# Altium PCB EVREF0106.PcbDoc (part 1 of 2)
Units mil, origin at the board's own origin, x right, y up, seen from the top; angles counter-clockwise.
Board outline 3543.31 x 1948.82 mil, 4 copper layers (Top Layer, GND, S2, Bottom Layer); 163 components, 42 nets, 581 pads, 707 vias.
Unrouted connection lines stored in the file: 3.
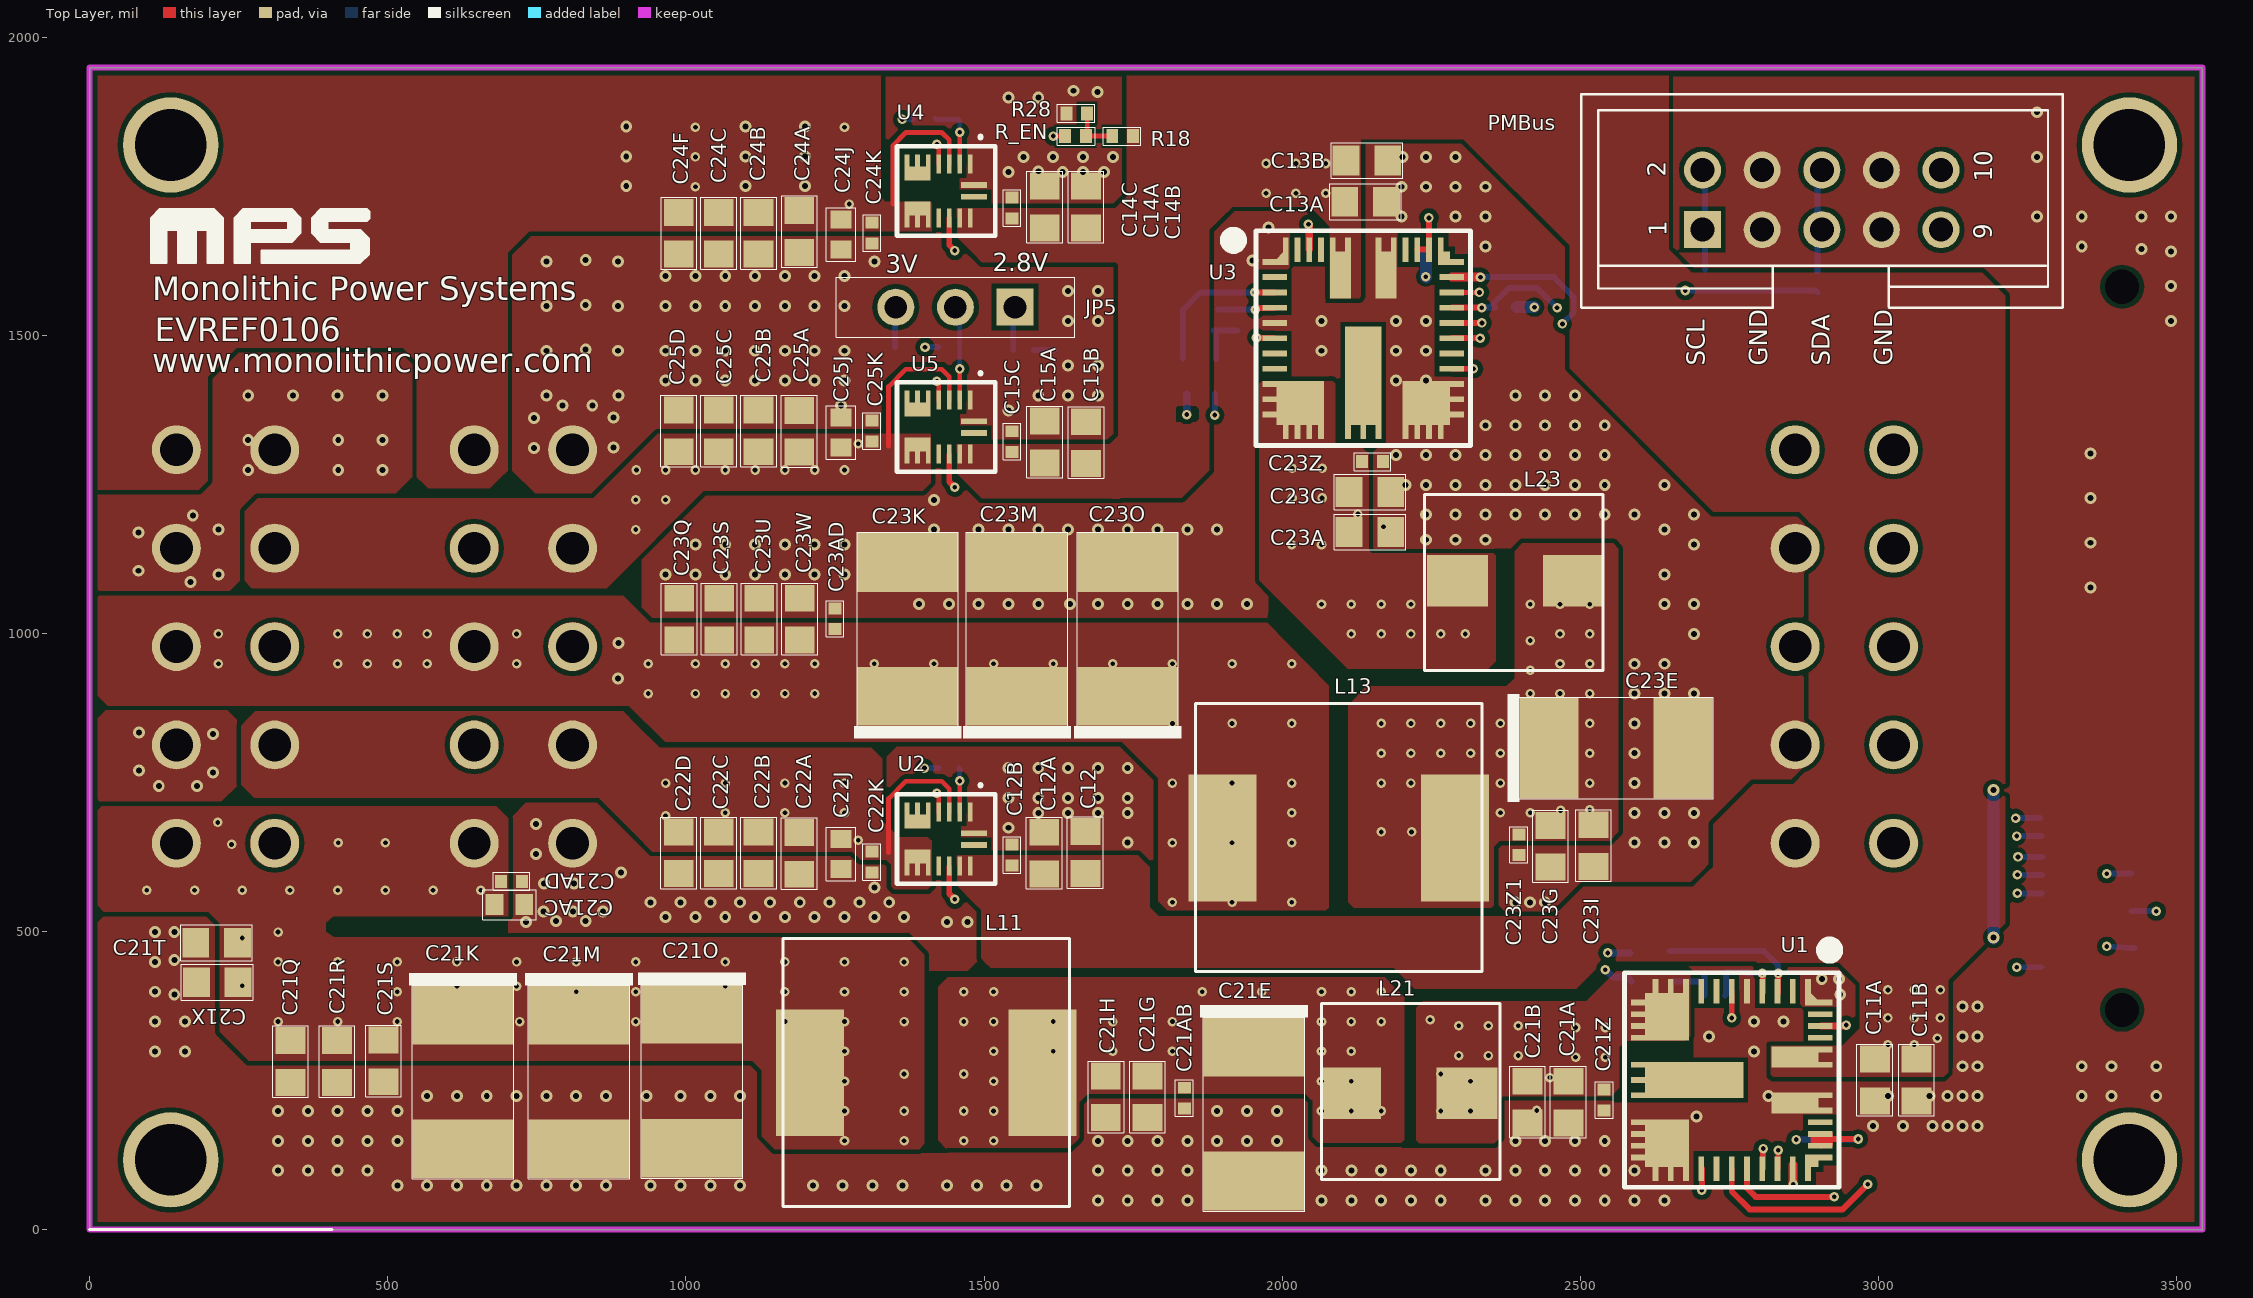
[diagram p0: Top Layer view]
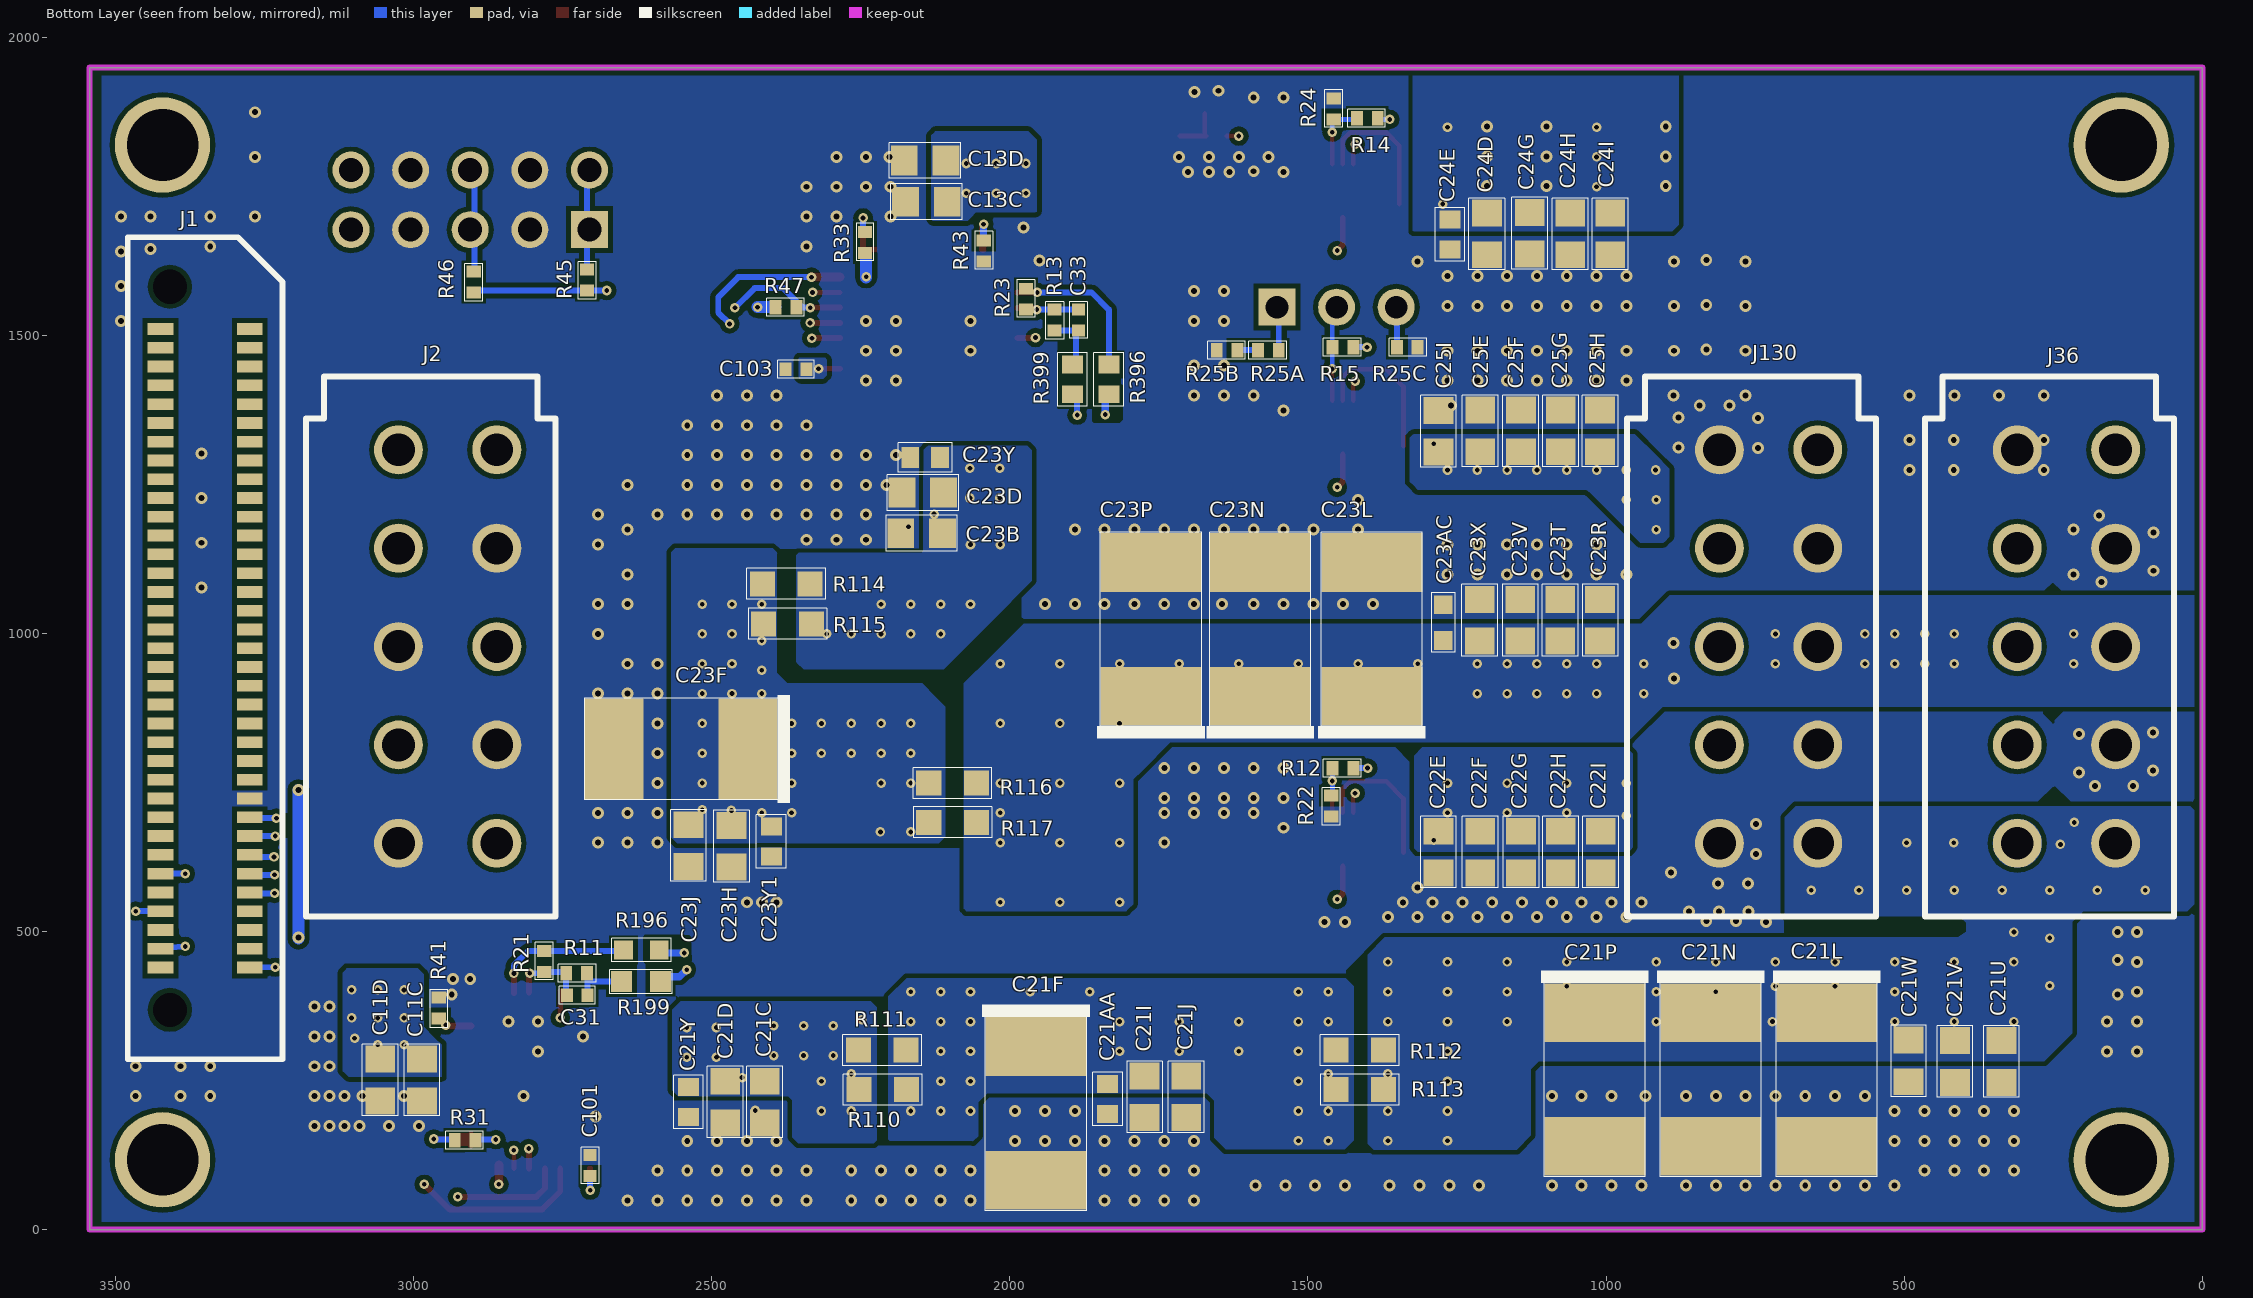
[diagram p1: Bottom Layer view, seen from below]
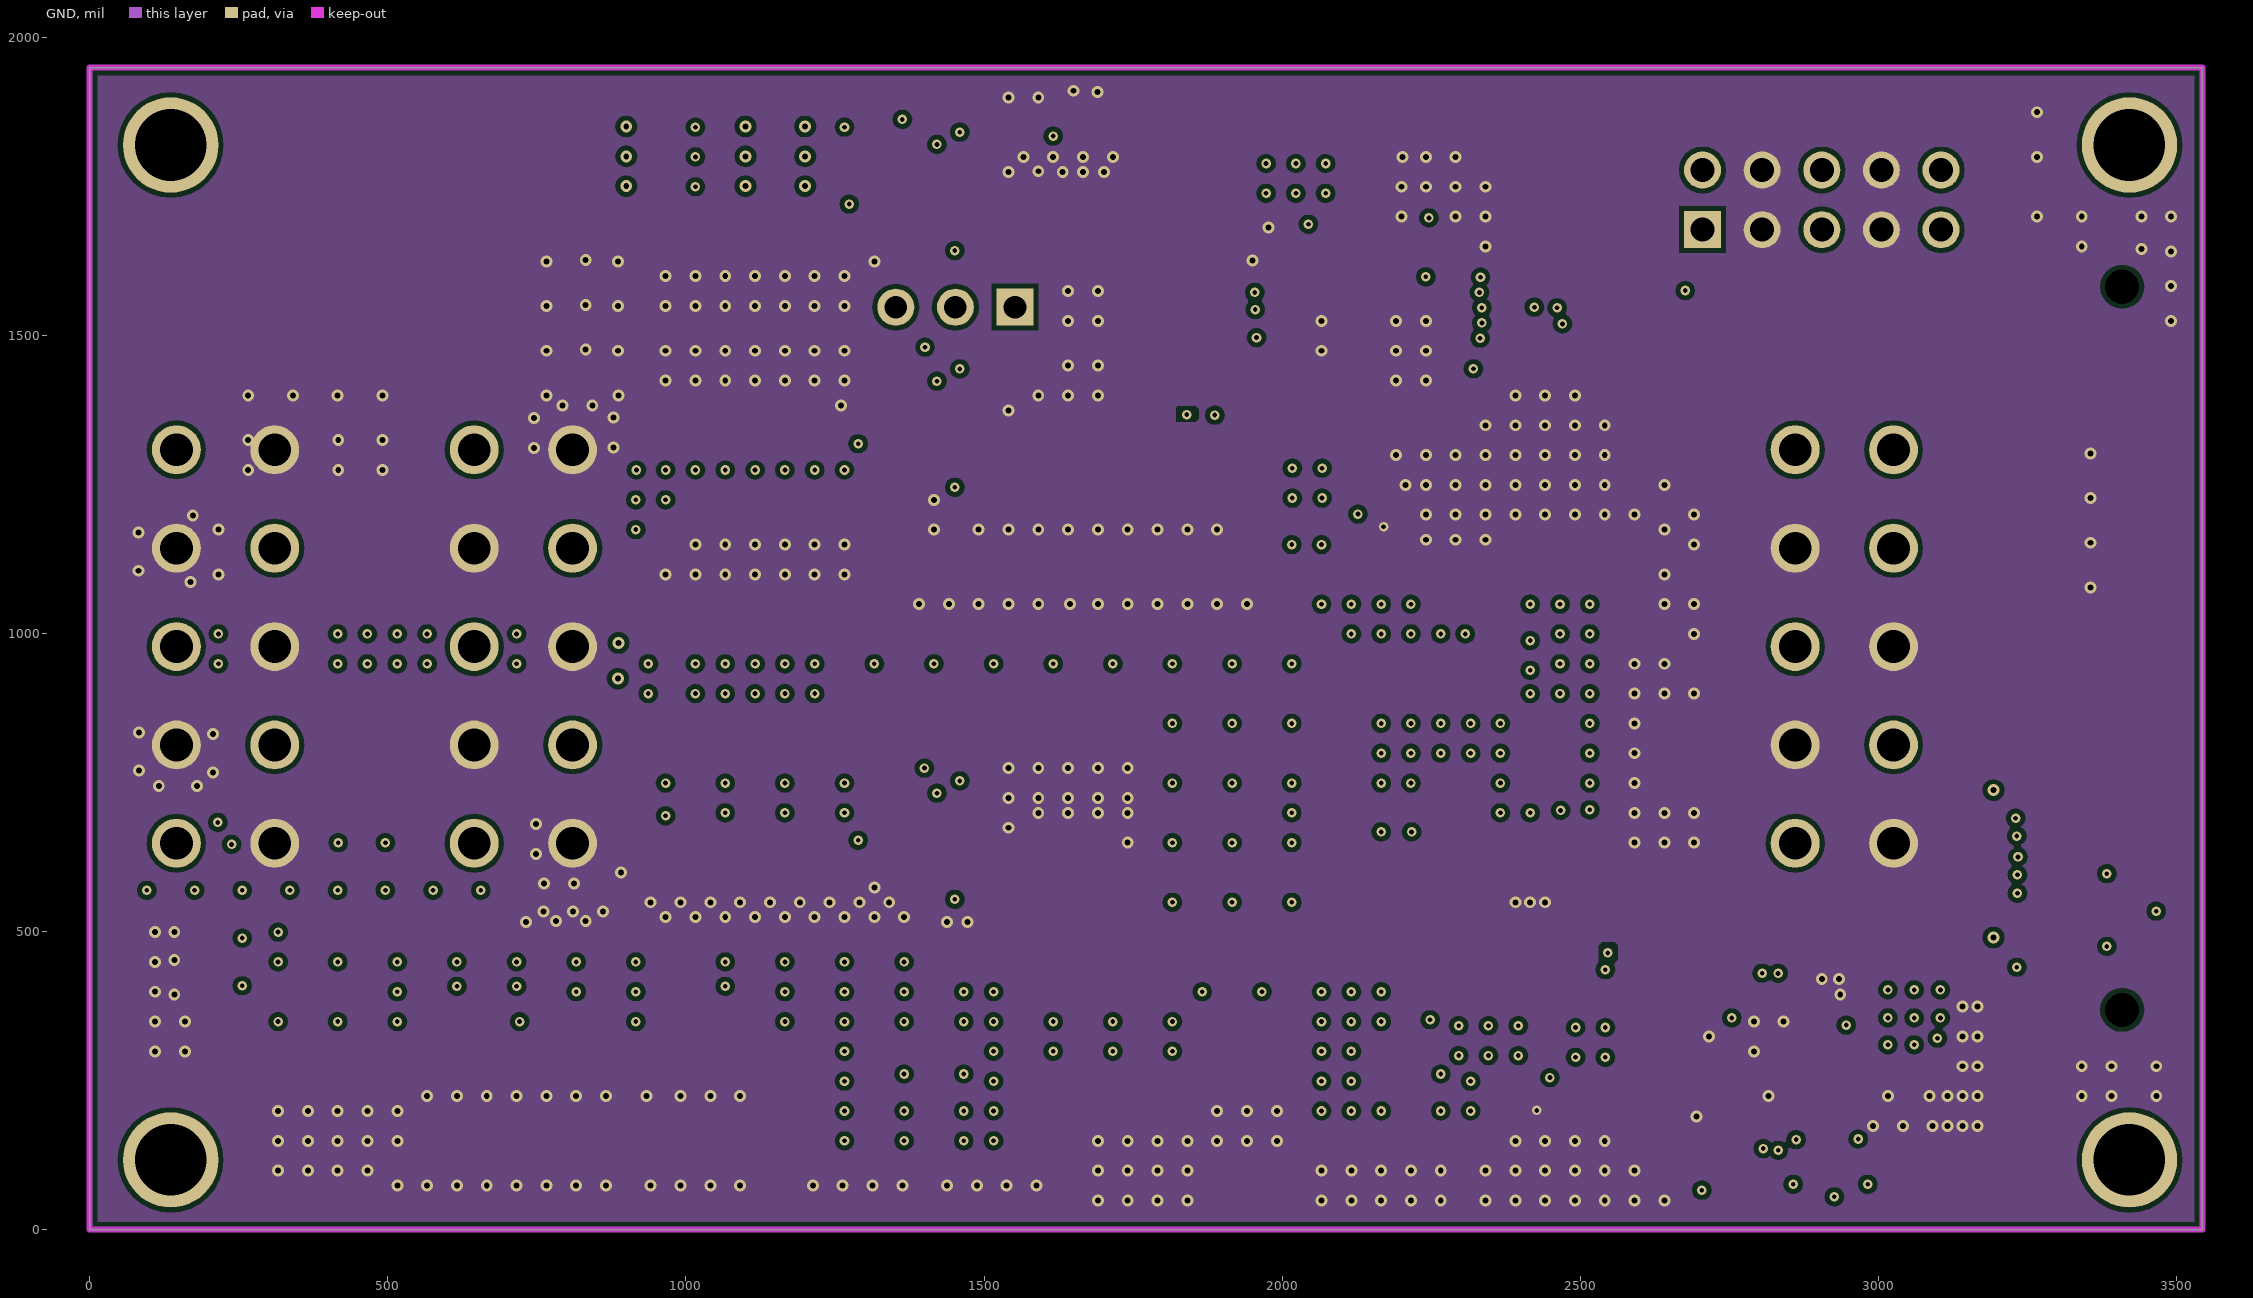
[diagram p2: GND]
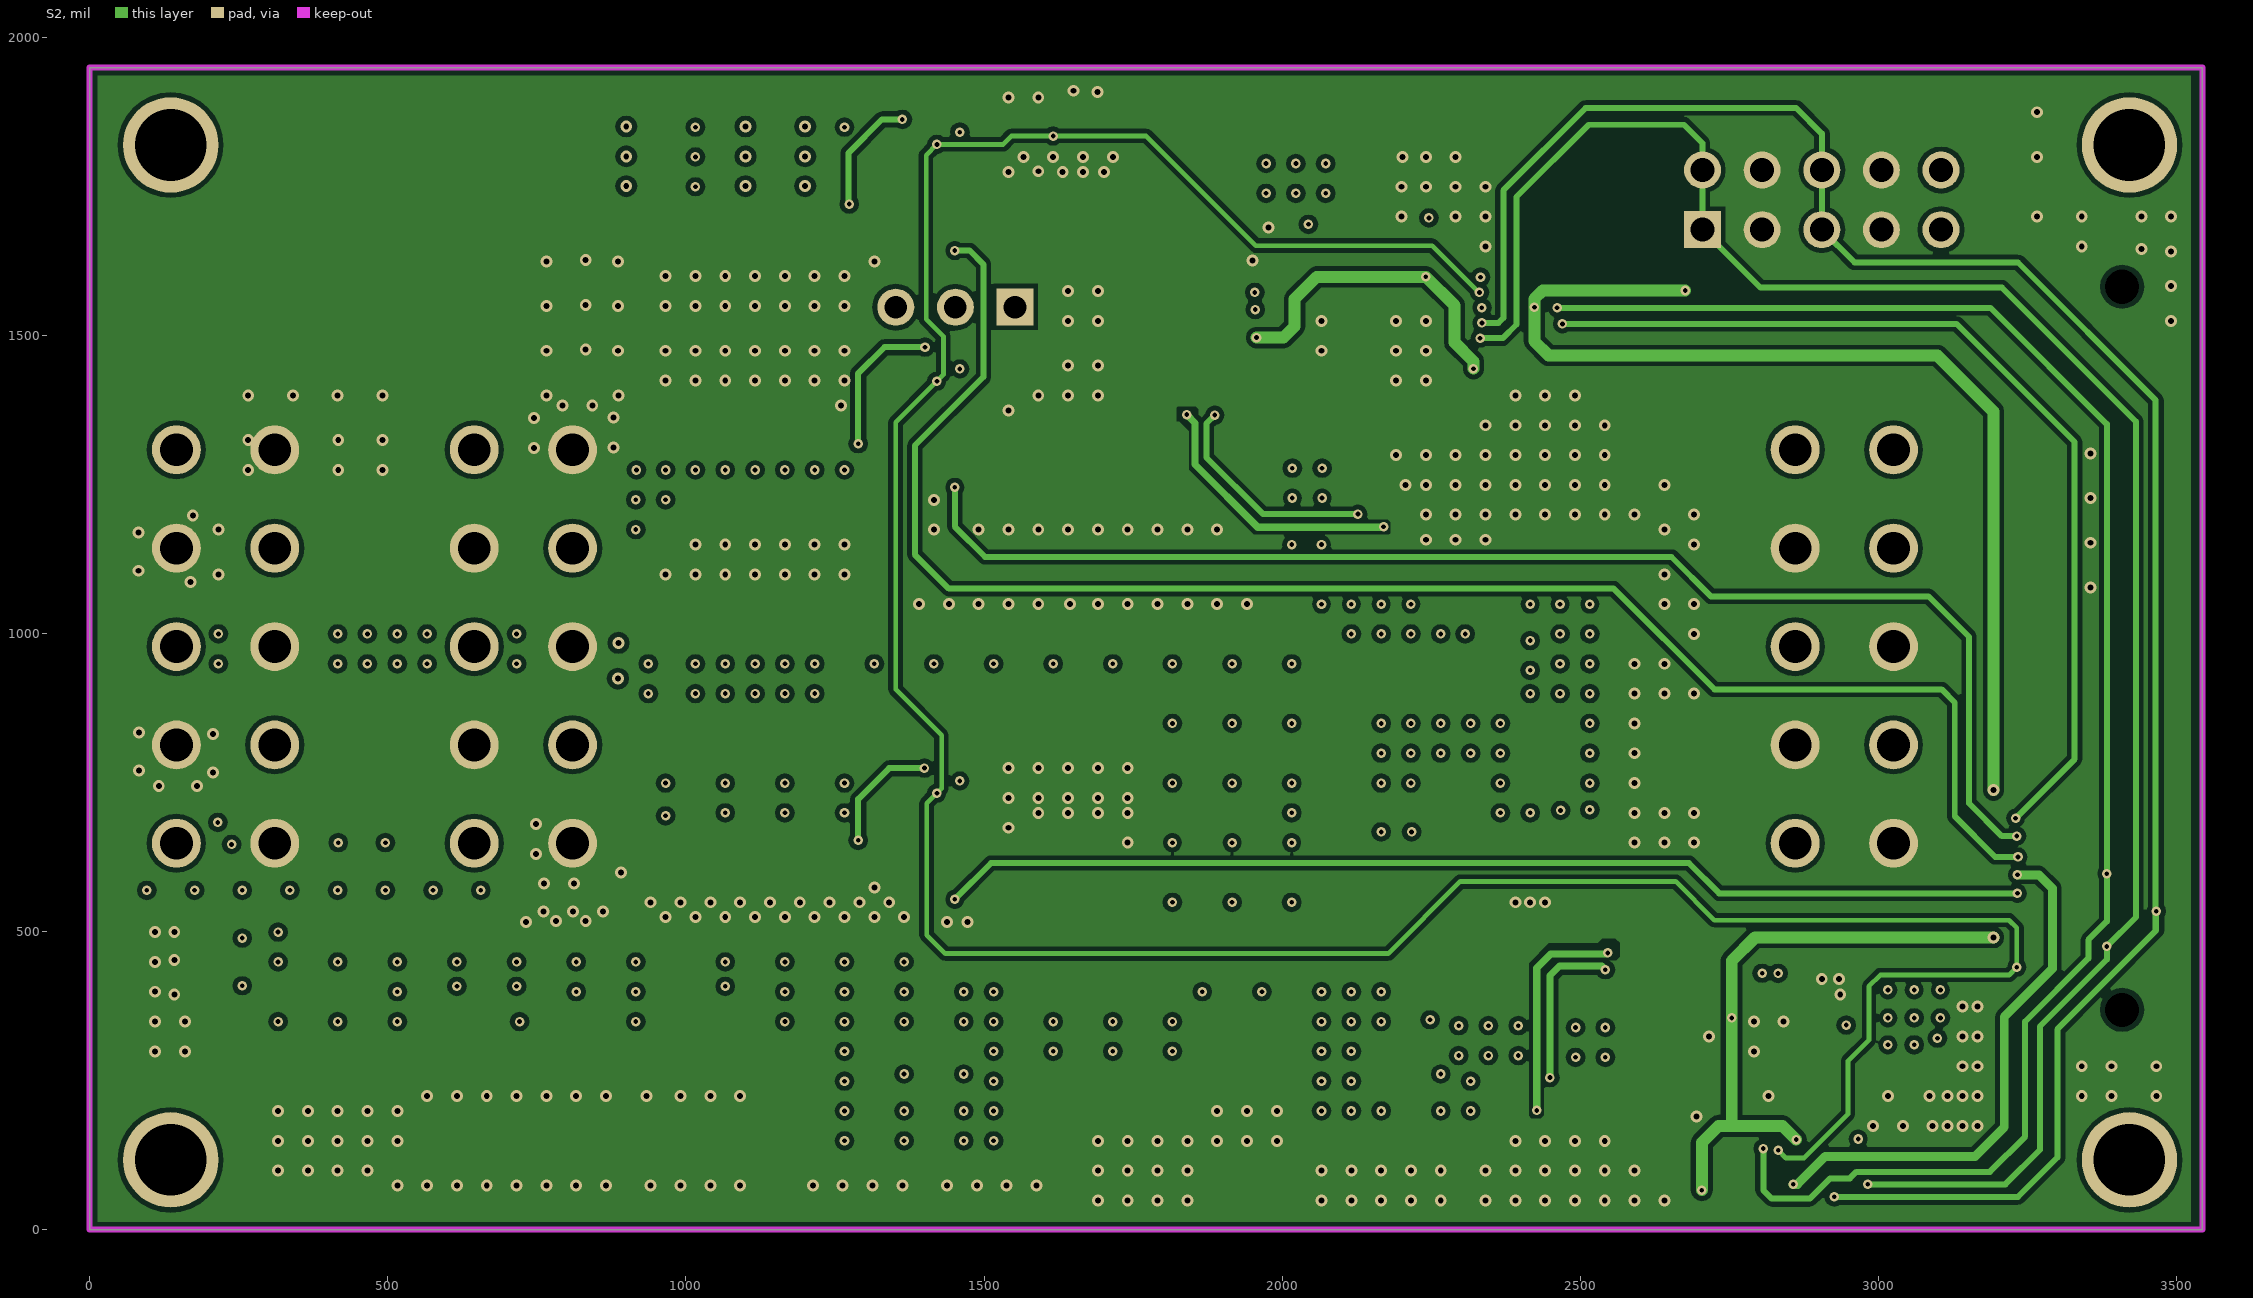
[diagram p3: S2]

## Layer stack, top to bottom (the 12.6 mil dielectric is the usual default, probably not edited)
Top Layer: signal copper 1.4
Dielectric: core 12.6, FR-4, Dk 4.8
GND: signal copper 1.4
Dielectric: prepreg 12.6, FR-4, Dk 4.8
S2: signal copper 1.4
Dielectric: core 12.6, FR-4, Dk 4.8
Bottom Layer: signal copper 1.4

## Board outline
0,1948.82 0,0 3543.31,0 3543.31,1948.82 0,1948.82

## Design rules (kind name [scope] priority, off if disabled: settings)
Clearance [All] p1: gap=8
ComponentClearance [All] p1: gap=10 collisioncheckmode=3 verticalgap=10 showdistances=TRUE
HoleSize [All] p1: absolutevalues=TRUE maxlimit=1000 minlimit=1 maxpercent=80.000 minpercent=20.000
MinimumSolderMaskSliver [All] p1: minsoldermaskwidth=2
PasteMaskExpansion [All] p1: expansion=-2
PlaneConnect [All] p1: planeconnectstyle=Direct reliefexpansion=20 reliefentries=4 reliefconductorwidth=10 reliefairgap=10
PolygonConnect [All] p1: connectstyle=Direct reliefconductorwidth=10 reliefentries=4 polygonreliefangle="90 Angle"
RoutingVias [All] p1: holewidth=11.81 width=19.68 viastyle="Through Hole" minholewidth=8 minwidth=18 maxholewidth=12 maxwidth=22
SilkToSilkClearance [All] p1: silktosilkclearance=2
SilkscreenOverComponentPads [All] p1: minsilkscreentomaskgap=0
SolderMaskExpansion [All] p1: expansion=3
Width [All] p1: maxlimit=50 minlimit=8 preferedwidth=10 minimp=50.000000 maximp=50.000000 favimp=50.000000
21 further rules are at their usual default settings.

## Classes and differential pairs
component class EVREF0106-1: C12 C12A C12B C14A C14B C14C C15A C15B C15C C22A C22B C22C C22D C22E C22F C22G C22H C22I C22J C22K C24A C24B C24C C24D C24E C24F C24G C24H C24I C24J C24K C25A C25B C25C C25D C25E C25F C25G C25H C25I C25J C25K J1 J2 J36 J130 JP5 PMBus R12 R14 R15 R18 R22 R24 R25A R25B R25C R28 R_EN U2 U4 U5
component class EVREF0106-2: C11A C11B C11C C11D C13A C13B C13C C13D C21A C21AA C21AB C21AC C21AD C21B C21C C21D C21E C21F C21G C21H C21I C21J C21K C21L C21M C21N C21O C21P C21Q C21R C21S C21T C21U C21V C21W C21X C21Y C21Z C23A C23AC C23AD C23B C23C C23D C23E C23F C23G C23H C23I C23J C23K C23L C23M C23N C23O C23P C23Q C23R C23S C23T C23U C23V C23W C23X C23Y C23Y1 C23Z C23Z1 C31 C33 C101 C103 L11 L13 L21 L23 R11 R13 R21 R23 R31 R33 R41 R43 R45 R46 R47 R110 R111 R112 R113 R114 R115 R116 R117 R196 R199 R396 R399 U1 U3

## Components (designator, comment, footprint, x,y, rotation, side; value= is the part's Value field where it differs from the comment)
C11A "16V" CAP0805 2994,216 r90 top
C11B "16V" CAP0805 3064,216 r90 top
C11C "16V" CAP0805 2986,216 r90 bottom
C11D "16V" CAP0805 3056,216 r90 bottom
C12 "16V" CAP0805 1670,667.53 r270 top
C12A "16V" CAP0805 1601,666.53 r270 top
C12B "0.1uF" CAP0402 1547,646 r270 top
C13A "16V" CAP0805 2175,1724 r180 top
C13B "16V" CAP0805 2177,1793 r180 top
C13C "16V" CAP0805 2175,1724 r180 bottom
C13D "16V" CAP0805 2177,1793 r180 bottom
C14A "16V" CAP0805 1602,1750 r270 top
C14B "16V" CAP0805 1671,1750 r270 top
C14C "0.1uF" CAP0402 1547,1731 r270 top
C15A "16V" CAP0805 1602,1356 r270 top
C15B "16V" CAP0805 1671,1355 r270 top
C15C "0.1uF" CAP0402 1547,1339 r270 top
C21A "6.3V" CAP0805 2480,178.81 r90 top
C21AA "16V" CAP0603#1 1836,244 r270 bottom
C21AB "6.3V" CAP0402 1836,238 r270 top
C21AC "16V" CAP0603#1 729,545 r180 top
C21AD "6.3V" CAP0402 725,584 r180 top
C21B "6.3V" CAP0805 2411.37,178.81 r90 top
C21C "6.3V" CAP0805 2411,179 r90 bottom
C21D "6.3V" CAP0805 2477.37,178.81 r90 bottom
C21E "6TPE330ML" POSCAP/D2 1953,306 r270 top
C21F "6TPE330ML" POSCAP/D2 1956,307 r270 bottom
C21G "6.3V" CAP0805 1774,187.81 r90 top
C21H "6.3V" CAP0805 1704,187.81 r90 top
C21I "6.3V" CAP0805 1774,187.81 r90 bottom
C21J "6.3V" CAP0805 1704,187.81 r90 bottom
C21K "6TPE330ML" POSCAP/D2 626,360 r270 top
C21L "6TPE330ML" POSCAP/D2 630,364 r270 bottom
C21M "6TPE330ML" POSCAP/D2 820.5,360 r270 top
C21N "6TPE330ML" POSCAP/D2 824.5,364 r270 bottom
C21O "6TPE330ML" POSCAP/D2 1010,361 r270 top
C21P "6TPE330ML" POSCAP/D2 1019,364 r270 bottom
C21Q "6.3V" CAP0805 337,247 r90 top
C21R "6.3V" CAP0805 415,247 r90 top
C21S "6.3V" CAP0805 493,248 r90 top
C21T "6.3V" CAP0805 178,481 r0 top
C21U "6.3V" CAP0805 337,247 r90 bottom
C21V "6.3V" CAP0805 415,247 r90 bottom
C21W "6.3V" CAP0805 493,248 r90 bottom
C21X "6.3V" CAP0805 179,415 r0 top
C21Y "16V" CAP0603#1 2539,239 r270 bottom
C21Z "6.3V" CAP0402 2540,235 r270 top
C22A "16V" CAP0805 1190,596 r90 top
C22B "16V" CAP0805 1122,597 r90 top
C22C "16V" CAP0805 1055,597 r90 top
C22D "16V" CAP0805 988,597 r90 top
C22E "16V" CAP0805 1281,598 r90 bottom
C22F "16V" CAP0805 1211,598 r90 bottom
C22G "16V" CAP0805 1143,598 r90 bottom
C22H "16V" CAP0805 1076,598 r90 bottom
C22I "16V" CAP0805 1009,598 r90 bottom
C22J "16V" CAP0603#1 1260,605 r90 top
C22K "6.3V" CAP0402 1312,599 r90 top
C23A "6.3V" CAP0805 2182,1170 r180 top
C23AC "16V" CAP0603#2 1319,1045 r270 bottom
C23AD "6.3V" CAP0402 1250,1042 r270 top
C23B "6.3V" CAP0805 2183,1168 r180 bottom
C23C "6.3V" CAP0805 2182,1237 r180 top
C23D "6.3V" CAP0805 2181,1236 r180 bottom
C23E "6TPE330ML" POSCAP/D2 2448,808 r0 top
C23F "6TPE330ML" POSCAP/D2 2439,806 r0 bottom
C23G "6.3V" CAP0805 2450,608 r90 top
C23H "6.3V" CAP0805 2467,608 r90 bottom
C23I "6.3V" CAP0805 2522,609 r90 top
C23J "6.3V" CAP0805 2539,609 r90 bottom
C23K "6TPE330ML" POSCAP/D2 1372,894.5 r90 top
C23L "6TPE330ML" POSCAP/D2 1393,894.5 r90 bottom
C23M "6TPE330ML" POSCAP/D2 1555.5,894.5 r90 top
C23N "6TPE330ML" POSCAP/D2 1580,894.5 r90 bottom
C23O "6TPE330ML" POSCAP/D2 1741,894.5 r90 top
C23P "6TPE330ML" POSCAP/D2 1763,894.5 r90 bottom
C23Q "6.3V" CAP0805 989,1059 r270 top
C23R "6.3V" CAP0805 1010,1057 r270 bottom
C23S "6.3V" CAP0805 1056,1059 r270 top
C23T "6.3V" CAP0805 1077,1057 r270 bottom
C23U "6.3V" CAP0805 1123,1059 r270 top
C23V "6.3V" CAP0805 1144,1057 r270 bottom
C23W "6.3V" CAP0805 1191,1059 r270 top
C23X "6.3V" CAP0805 1212,1057 r270 bottom
C23Y "16V" CAP0603#1 2117,1295 r0 bottom
C23Y1 "16V" CAP0603#1 2400,676 r270 bottom
C23Z "6.3V" CAP0402 2134,1288 r0 top
C23Z1 "6.3V" CAP0402 2397,663 r270 top
C24A "16V" CAP0805 1190,1639 r90 top
C24B "16V" CAP0805 1122,1636 r90 top
C24C "16V" CAP0805 1055,1636 r90 top
C24D "16V" CAP0805 1200,1635 r90 bottom
C24E "Cap" CAP0603#1 1262,1644 r90 bottom
C24F "16V" CAP0805 988,1636 r90 top
C24G "16V" CAP0805 1128,1636 r90 bottom
C24H "16V" CAP0805 1060,1635 r90 bottom
C24I "16V" CAP0805 993,1635 r90 bottom
C24J "16V" CAP0603#1 1260,1644 r90 top
C24K "6.3V" CAP0402 1312,1654 r90 top
C25A "16V" CAP0805 1190,1374 r270 top
C25B "16V" CAP0805 1122,1374.72 r270 top
C25C "16V" CAP0805 1055,1374.72 r270 top
C25D "16V" CAP0805 988,1374.72 r270 top
C25E "16V" CAP0805 1211,1374.72 r270 bottom
C25F "16V" CAP0805 1143,1374.72 r270 bottom
C25G "16V" CAP0805 1076,1374.72 r270 bottom
C25H "16V" CAP0805 1010,1374.72 r270 bottom
C25I "16V" CAP0805 1281,1374 r270 bottom
C25J "16V" CAP0603#1 1260,1362 r270 top
C25K "6.3V" CAP0402 1312,1357 r270 top
C31 "50V" CAP0402 2708,393 r0 bottom
C33 "50V" CAP0402 1885,1508 r90 bottom
C101 "16V" CAP0402 2704,125 r270 bottom
C103 "16V" CAP0402 2376,1443 r180 bottom
J1 "Header 70 Pins" ERM8-035-XX.X-X-DV 3349.53,975 r270 bottom
J2 "Header 5X2A" J1 2942.83,977.99 r0 bottom locked
J36 "Header 5X2A" J1 227.95,977.99 r0 bottom locked (schematic designator J3)
J130 "Header 5X2A" J1 727.48,977.99 r0 bottom locked
JP5 "SWITCH_SPDT_WE" JUMPER/3PIN-WE450301014042 1552,1547 r180 top
L11 "Inductor" 7443310220 1598,263 r180 top
L13 "Inductor" 7443310220 2290,657 r180 top
L21 "Inductor" 744307022 2310,229 r180 top
L23 "Inductor" 744307022 2294,1088 r0 top
PMBus "*" "I2C Connector" 2705,1677 r90 top
R11 "" RES0402 2744,430 r180 bottom
R12 "" RES0402 1424,774 r0 bottom
R13 "" RES0402 1925,1543 r270 bottom
R14 "" RES0402 1383,1864 r0 bottom
R15 "" RES0402 1424,1480 r0 bottom
R18 "" RES0402 1750,1834 r180 top
R21 "" RES0402 2781,432 r90 bottom
R22 "" RES0402 1461,728 r270 bottom
R23 "" RES0402 1973,1543 r90 bottom
R24 "" RES0402 1457,1862 r90 bottom
R25A "" RES0402 1549,1475 r0 bottom
R25B "" RES0402 1618,1475 r0 bottom
R25C "" RES0402 1351,1480 r180 bottom
R28 "" RES0402 1673,1872 r180 top
R31 "" RES0402 2896,150 r0 bottom
R33 "" RES0402 2243,1638 r90 bottom
R41 "" RES0402 2958,389 r270 bottom
R43 "" RES0402 2044,1624 r90 bottom
R45 "" RES0402 2709,1610 r270 bottom
R46 "" RES0402 2899,1607 r270 bottom
R47 "" RES0402 2358,1547 r0 bottom
R110 "" RES/0805 2253,235 r180 bottom
R111 "" RES/0805 2254,301 r180 bottom
R112 "" RES/0805 1453.22,301 r180 bottom
R113 "" RES/0805 1453.22,235 r180 bottom
R114 "" RES/0805 2335,1083 r0 bottom
R115 "" RES/0805 2333,1016 r0 bottom
R116 "" RES/0805 2136,749 r180 bottom
R117 "" RES/0805 2136,683 r180 bottom
R196 "0" RES/0603 2588,469 r0 bottom (schematic designator R199)
R199 "" RES0603#1 2586,416 r0 bottom
R396 "0R" RES0603#2 1834,1401 r90 bottom
R399 "" RES0603#2 1895,1401 r90 bottom
R_EN "" RES0402 1636,1834 r0 top
U1 "DC/DC Power Module" "QFN-45 (8X8)" 2754,251 r270 top
U2 "MPM3833C" MPM3833 1424,655 r270 top
U3 "DC/DC Power Module" "QFN-45 (8X8)" 2136,1495 r0 top
U4 "MPM3833C" MPM3833 1424,1742 r270 top
U5 "MPM3833C" MPM3833 1424,1346 r270 top

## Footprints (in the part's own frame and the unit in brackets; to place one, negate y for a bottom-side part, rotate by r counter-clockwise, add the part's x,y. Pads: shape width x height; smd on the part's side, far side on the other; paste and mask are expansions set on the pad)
744307022 [mm]
  rect 2.6x2.2 smd mask+0.025: 1(0,0) 2(4.953,0)
  silkscreen extent -1.4,-3.81 6.2,3.69
7443310220 [mm]
  rect 2.9x5.4 smd mask+0.025: 1(0,0) 2(9.906,0)
  silkscreen extent -1.14,-5.71 11.05,5.69
CAP0402 [mil]
  rect 20x22 smd paste-2 mask+2: 1(0,0) 2(35,0)
  silkscreen extent -13,-15 48,15, body extent -2,-10 38,10, height 22
CAP0603#1 [mil]
  rect 30x35 smd: 1(0,0) 2(50,0)
  silkscreen extent -20,-25 70,25, body extent -5,-15 55,15, height 20
CAP0603#2 [mil]
  rect 31.5x31.5 smd: 1(-3,45.92) 2(57,45.92)
  silkscreen extent -23,26 77,66, body extent -3,31 57,61, height 20
CAP0805 [mil]
  rect 45x50 smd: 1(0,0) 2(70,0)
  silkscreen extent -25,-30 95,30, body extent -20,-25 90,25, height 50
ERM8-035-XX.X-X-DV [mm]
  rect 0.5x1.1 smd: 1(-13.6,1.9) 2(-13.6,-1.9) 3(-12.8,1.9) 4(-12.8,-1.9) 5(-12,1.9) 6(-12,-1.9) 7(-11.2,1.9) 8(-11.2,-1.9) 9(-10.4,1.9) 10(-10.4,-1.9) 11(-9.6,1.9) 12(-9.6,-1.9) 13(-8.8,1.9) 14(-8.8,-1.9) 15(-8,1.9) 16(-8,-1.9) 17(-7.2,1.9) 18(-7.2,-1.9) 19(-6.4,1.9) 20(-6.4,-1.9) 21(-5.6,1.9) 22(-5.6,-1.9) 23(-4.8,1.9) 24(-4.8,-1.9) 25(-4,1.9) 26(-4,-1.9) 27(-3.2,1.9) 28(-3.2,-1.9) 29(-2.4,1.9) 30(-2.4,-1.9) 31(-1.6,1.9) 32(-1.6,-1.9) 33(-0.8,1.9) 34(-0.8,-1.9) 35(0,1.9) 36(0,-1.9) 37(0.8,1.9) 38(0.8,-1.9) 39(1.6,1.9) 40(1.6,-1.9) 41(2.4,1.9) 42(2.4,-1.9) 43(3.2,1.9) 44(3.2,-1.9) 45(4,1.9) 46(4,-1.9) 47(4.8,1.9) 48(4.8,-1.9) 49(5.6,1.9) 50(5.6,-1.9) 51(6.4,1.9) 52(6.4,-1.9) 53(7.2,1.9) 54(7.2,-1.9) 55(8,1.9) 56(8,-1.9) 57(8.8,1.9) 58(8.8,-1.9) 59(9.6,1.9) 60(9.6,-1.9) 61(10.4,1.9) 62(10.4,-1.9) 63(11.2,1.9) 64(11.2,-1.9) 65(12,1.9) 66(12,-1.9) 67(12.8,1.9) 68(12.8,-1.9) 69(13.6,1.9) 70(13.6,-1.9)
  round 0 hole 1.45: MH1(-15.4,-1.5) MH2(15.4,-1.5)
  silkscreen extent -17.51,-3.3 17.51,3.3
"I2C Connector" [mil]
  rect 62x62 hole 40.16: 1(0,0)
  round 62 hole 40.16: 2(100,0) 3(0,-100) 4(100,-100) 5(0,-200) 6(100,-200) 7(0,-300) 8(100,-300) 9(0,-400) 10(100,-400)
  silkscreen extent -131,-604 227,204
J1 [mil]
  round 82 hole 55: 1(-82.48,330) 2(-82.48,165.04) 3(-82.48,0.08) 4(-82.48,-164.88) 5(-82.48,-330) 6(82.48,330) 7(82.48,165.04) 8(82.48,0.08) 9(82.48,-164.88) 10(82.48,-329.84)
  silkscreen extent -180,-452 238,452
JUMPER/3PIN-WE450301014042 [mil]
  rect 62x62 hole 38: 1(0,0)
  round 62 hole 38: 2(100,0) 3(200,0)
  silkscreen extent -100,-50 300,50
MPM3833 [mm]
  rect 0.8x0.2 smd: 1(-1.15,1.35) 2(-1.15,0.9) 3(-1.15,0.45) 4(-1.15,0) 11(1.15,0) 12(1.15,0.45) 13(1.15,0.9) 14(1.15,1.35)
  rect 1.1x0.2 smd: 5(-1,-0.45) 6(-1,-0.9) 7(-1,-1.35) 8(1,-1.35) 9(1,-0.9) 10(1,-0.45)
  rect 0.6x1.1 smd: 5(-0.75,-0.9) 10(0.75,-0.9)
  rect 0.25x1.1 smd: 15(0.25,1.5) 16(-0.25,1.5)
  silkscreen extent -2.31,-1.78 1.91,2.41
POSCAP/D2 [mm]
  rect 2.5x4.3 smd paste-25.4 mask+0.051: 1(0,0) 2(5.699,0)
  silkscreen extent -1.78,-2.29 6.98,2.29, body extent -0.64,-2.16 6.35,2.16, height 2.03
"QFN-45 (8X8)" [mm] "QFN, 44-Leads, Body 8.00x8.00mm, Pitch 0.50mm/0.65mm, IPC Medium Density"
  rect 1.05x0.25 smd mask+0.051: 1(-3.775,3.25) 2(-3.775,2.6) 3(-3.775,1.95) 4(-3.775,1.3) 5(-3.775,0.65) 6(-3.775,0) 7(-3.775,-0.65) 8(-3.775,-1.3) 9(-3.775,-1.95) 10(-3.775,-2.6) 11(-3.775,-3.25) 23(3.775,-3.25) 24(3.775,-2.6) 25(3.775,-1.95) 26(3.775,-1.3) 27(3.775,-0.65) 28(3.775,0) 29(3.775,0.65) 30(3.775,1.3) 31(3.775,1.95) 32(3.775,2.6) 33(3.775,3.25)
  rect 0.3x0.4 smd rot 135.1 mask+0.051: 1(-3.461,3.407)
  rect 2.025x1.875 smd mask+0.051: 9(-2.688,-2.762) 19(2.688,-2.762)
  rect 0.25x1.175 smd mask+0.051: 12(-3.3,-3.712) 34(3.3,3.712) 45(-3.3,3.712)
  rect 0.25x1.05 smd mask+0.051: 13(-2.8,-3.775) 14(-2.3,-3.775) 15(-1.8,-3.775) 16(-0.65,-3.775) 17(0,-3.775) 18(0.65,-3.775) 19(1.8,-3.775) 20(2.3,-3.775) 21(2.8,-3.775) 22(3.3,-3.775) 35(2.8,3.775) 36(2.3,3.775) 37(1.8,3.775) 38(1.3,3.775) 39(0.65,3.775) 40(-0.65,3.775) 41(-1.3,3.775) 42(-1.8,3.775) 43(-2.3,3.775) 44(-2.8,3.775)
  rect 1.55x4.2 smd mask+0.051: 16(0,-1.6)
  rect 0.525x0.575 smd mask+0.051: 33(3.437,3.413)
  rect 0.9x2 smd mask+0.051: 38(0.975,2.7) 40(-0.975,2.7)
  silkscreen extent -5.73,-4.57 4.57,4.57, body extent -4,-4 4,4, height 1.6
RES0402 [mil]
  rect 20x24 smd: 1(0,0) 2(35,0)
  silkscreen extent -13,-15 50,15, body extent -2,-10 38,10, height 22
RES0603#1 [mil]
  rect 35x35 smd: 1(0,0) 2(65,0)
  silkscreen extent -20,-20 85,20
RES0603#2 [mil]
  rect 30x35 smd paste-2 mask+2: 1(0,0) 2(50,0)
  silkscreen extent -20,-25 70,25, body extent -5,-15 55,15, height 32
RES/0603 [mm]
  rect 0.8x0.8 smd: 1(0,0) 2(1.524,0)
  silkscreen extent -0.51,-0.51 2.03,0.51
RES/0805 [mil]
  rect 42x42 smd paste+0 mask+4: 1(0,0) 2(80,0)
  silkscreen extent -26,-26 106,26

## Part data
C11A C11B C11C C11D C12 C12A C12B C13A C13B C13C C13D C14A C14B C14C C15A C15B C15C C21A C21AA C21AB C21AC C21AD C21B C21C C21D C21G C21H C21I C21J C21Q C21R C21S C21T C21U C21V C21W C21X C21Y C21Z C22A C22B C22C C22D C22E C22F C22G C22H C22I C22J C22K C23A C23AC C23AD C23B C23C C23D C23G C23H C23I C23J C23Q C23R C23S C23T C23U C23V C23W C23X C23Y C23Y1 C23Z C23Z1 C24A C24B C24C C24D C24F C24G C24H C24I C24J C24K C25A C25B C25C C25D C25E C25F C25G C25H C25I C25J C25K C31 C33 C101 C103: library part Cap, "Capacitor"
C21E C21F C21K C21L C21M C21N C21O C21P C23E C23F C23K C23L C23M C23N C23O C23P: library part POSCAP/C2, "330uF/6.5V/POSCAP D2"
C24E: "Capacitor"
J2 J36 J130: "Header, 5-Pin, Dual row"
JP5: "{Description}"
PMBus: library part "HEADER 5X2", "HEADER 5X2"
R11 R12 R13 R14 R15 R18 R21 R22 R23 R24 R25A R25B R25C R28 R31 R33 R41 R43 R45 R46 R47 R110 R111 R112 R113 R114 R115 R116 R117 R199 R399 R_EN: library part 1W-1, "Film Res., 1%"
R196 R396: library part RES0603, "{Description}"
U1 U3: library part MPM3695-10, "MODULE ?14V, 10A, Scalable, Ultra-Thin, DC/DC Power Module with PMBus"
U2 U4 U5: library part MPM3833

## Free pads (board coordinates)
  round 160 hole 120: 0(136,117) 0(136,1819) 0(3421,117) 0(3421,1819)

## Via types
v1: diameter 20, hole 10, Top Layer to Bottom Layer, tented both sides, 417 vias
v2: diameter 16, hole 8, Top Layer to Bottom Layer, tented both sides, 290 vias

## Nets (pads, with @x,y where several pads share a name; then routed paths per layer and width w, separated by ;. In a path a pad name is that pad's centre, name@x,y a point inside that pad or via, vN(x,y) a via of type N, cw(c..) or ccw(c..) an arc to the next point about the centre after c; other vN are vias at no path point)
ADC_AVCC: C21AC.2 C21AD.2 C21K.1 C21L.1 C21M.1 C21N.1 C21O.1 C21P.1 C21Q.2 C21R.2 C21S.2 C21T.2 C21U.2 C21V.2 C21W.2 C21X.2 J36.1 J130.1 L11.2 R112.2 R113.2
  other v2: 1266,149 1366,149 1266,199 1366,199 1266,249 1366,261 1266,299 316,349 416,349 516,349 721,349 916,349 1166,349 1266,349 1366,349 516,399 816,399 916,399 1166,399 1266,399 1366,399 616,408 716,408 1066,408 256,409 316,449 416,449 516,449 616,449 716,449 816,449 916,449 1066,449 1166,449 1266,449 1366,449 256,489 316,499 96,569 176,569 256,569 336,569 416,569 496,569 576,569 656,569 238,646 417,649 496,649 215,683
ADC_AVCC_ADDR: R41.2 U1.43 | length 40.9
  Top Layer w12: U1.43@2903.62,341.55 v2@2944.55,341.55
  other v2: 2946,343
ADC_AVCC_PG: J1.59 U1.32 | length 969.5
  Top Layer w15: v2(2857,76) U1.32@2857,108.38
  S2 w15: v2(2857,76) 2864,76 2911,123 3162,123 3211,172 3211,357 3292,438 3292,572 3268.95,595.05 v2(3233.05,595.05)
  Bottom Layer w10: v2(3233.05,595.05) J1.59@3274.38,595.05
ADC_AVCC_TAKE: R31.2 U1.35 U1.36 | length 105.6
  Top Layer w10: U1.35@2903.62,140.76 U1.36@2903.62,160.45 ; 2906.86,152 v2@2960,152
  Bottom Layer w10: R31.2@2931.24,151 v2@2964,151
  other v2: 2966,152
ADC_AVCC_VOSN: R21.2 R196.2 U1.3 | length 238.2
  Top Layer w10: U1.3@2831.77,396.63 2831.77,399.62 v2(2831.77,429.78)
  Bottom Layer w10: R196.2@2650,467 R21.2@2781,467 2808,467 2831.77,443.23 v2(2831.77,429.78)
ADC_AVCC_VOSP: C31.2 R11.1 R21.1 U1.4 | length 133.5
  Top Layer w10: U1.4@2806.77,397.63 2806.77,399.62 2806.77,430 v2@2806.77,430.78
  Bottom Layer w10: C31.2@2743,393 2744,394 R11.1@2744,430 2746,432 R21.1@2781,432 ; R21.1@2779.89,430 v2(2805,430)
ADC_AVCCAUX: C22A.2 C22B.2 C22C.2 C22D.2 C22E.2 C22F.2 C22G.2 C22H.2 C22I.2 C22J.2 C22K.2 J36.7 J130.7 R12.1 U2.3 U2.8 U2.9 U2.10 | length 475.7
  Top Layer w8: 1340,632 1340,723 1369,752 1429.28,752 1441.72,739.57 U2.3@1441.72,700.28 U2.3@1441.72,699.28
  S2 w10: v2(1289,653) 1289,722 1341,774 v2(1400,774)
  Bottom Layer w10: v2(1400,774) R12.1@1424,774
  other v2: 966,694 1066,699 1166,699 1266,699 966,749 1066,749 1166,749 1266,749
ADC_AVCCAUX_PG: J1.61 U2.12 | length 1928.3
  Top Layer w10: U2.12@1441.72,608.72 1441.72,563.28 v2(1451,554)
  S2 w10: v2(1451,554) 1512,615 2682,615 2732.95,564.05 v2(3233.05,564.05)
  Bottom Layer w10: v2(3233.05,564.05) J1.61@3274.38,564.05
ADC_VCC: C101.2 R31.1 R45.2 R46.2 R47.2 U1.6 U1.26 | length 3430.5
  Top Layer w10: v2(2703.82,66.18) U1.26@2703.82,102.38 ; v2@2754,354 U1.6@2754,399.62
  S2 w20: v2(2676,1575) 2437,1575 2423,1561 v2(2423,1547) 2423,1490 2447,1466 3099,1466 3193,1372 v1(3193,737) ; v2(2703.82,66.18) 2703.82,145.82 2732,174 2839,174 v2(2862,151) ; 2754,175 2754,427 ; 2754,412 2754,451 2793,490 v1(3193,490)
  Bottom Layer w10: v2(2676,1575) R45.2@2709,1575 2895,1575 R46.2@2898,1572 ; v2(2703.82,66.18) C101.2@2703.82,89.82 ; v2(2862,151) R31.1@2896,151
  Bottom Layer w20: R47.2@2393,1547 v2(2423,1547) ; v1@3193,488 v1(3193,490) v1(3193,737)
  other v2: 2754,355
ALT: J1.60 R47.1 U1.30 U3.30 | length 3101.1
  Top Layer w10: U3.30@2284.62,1546.18 v2(2334.82,1546.18) ; U1.30@2806.18,102.38 v2@2806.18,134.76
  S2 w10: v2(2461,1546) 3188,1546 3383.05,1350.95 v2(3383.05,597.05) 3383.05,517.05 3352,486 3352,455 3246,349 3246,156 3187,97 2963,97 2952,86 2919,86 2885,52 2821,52 2807,66 v2(2807,136)
  Bottom Layer w10: v2(2334.82,1546.18) 2347,1546.18 ; R47.1@2358,1547 2357.18,1546.18 2347,1546.18 ; v2(2461,1546) 2428,1579 2379.82,1579 2347,1546.18 ; v2(3383.05,597.05) J1.60@3424.38,597.05
DAC_AVCC: C23AC.2 C23AD.2 C23K.1 C23L.1 C23M.1 C23N.1 C23O.1 C23P.1 C23Q.2 C23R.2 C23S.2 C23T.2 C23U.2 C23V.2 C23W.2 C23X.2 J36.3 J130.3 L13.2 R116.2 R117.2
  other v1: 886,924 887,984
  other v2: 1816,549 1916,549 2016,549 1816,649 1916,649 2016,649 2016,699 1816,749 1916,749 2016,749 1816,849 1916,849 2016,849 937,899 1016,899 1066,899 1116,899 1166,899 1216,899 216,949 416,949 466,949 516,949 566,949 716,949 937,949 1016,949 1066,949 1116,949 1166,949 1216,949 1316,949 1416,949 1516,949 1616,949 1716,949 1816,949 1916,949 2016,949 216,999 416,999 466,999 516,999 566,999 716,999
DAC_AVCC_ADDR: R43.2 U3.43 | length 67.9
  Top Layer w12: U3.43@2045.45,1643.62 v2@2045.45,1684.55
  Bottom Layer w12: R43.2@2044,1659 v2(2044,1686)
DAC_AVCC_PG: J1.53 U3.32 | length 1925.4
  Top Layer w15: U3.32@2284.62,1597.36 v2(2332.64,1597.36)
  S2 w10: v2(2470,1519) 3131,1519 3329,1321 3329,789 v2(3230.05,690.05)
  Bottom Layer w10: v2(2332.64,1597.36) 2455.64,1597.36 2489,1564 2489,1538 v2(2470,1519) ; v2(3230.05,690.05) J1.53@3271.38,690.05
DAC_AVCC_TAKE: R33.2 U3.35 U3.36 | length 88.4
  Top Layer w10: U3.36@2226.55,1643.62 U3.35@2246.24,1643.62 v2(2246.24,1696.76)
  Bottom Layer w10: R33.2@2246.24,1681.24 v2(2246.24,1696.76)
DAC_AVCC_VOSN: R23.2 R396.2 U3.3 | length 247.3
  Top Layer w10: v2(1954.23,1571.77) U3.3@1987.38,1571.77
  Bottom Layer w10: R396.2@1834,1461 1834,1543 1862.77,1571.77 v2(1954.23,1571.77)
DAC_AVCC_VOSP: C33.2 R13.1 R23.1 U3.4 | length 96
  Top Layer w10: v2@1954.23,1545.77 U3.4@1987.38,1545.77
  Bottom Layer w10: C33.2@1892,1543 v2(1954.9,1543)
DAC_AVCCAUX: C24A.2 C24B.2 C24C.2 C24D.2 C24E.2 C24F.2 C24G.2 C24H.2 C24I.2 C24J.2 C24K.2 J36.5 J130.5 R14.1 U4.3 U4.8 U4.9 U4.10 | length 465.5
  Top Layer w8: 1347,1720 1347,1818 1369,1840 1429.28,1840 1441.72,1827.57 U4.3@1441.72,1787.28
  S2 w10: v2@1273,1720 1273,1806 1329,1862 v2(1363,1862)
  Bottom Layer w8: v2(1363,1862) R14.1@1382,1862
  other v1: 900,1750 1100,1750 1200,1750 900,1800 1100,1800 1200,1800 900,1850 1100,1850 1200,1850
  other v2: 1274,1720 1016,1749 1016,1799 1016,1849 1266,1849
DAC_AVCCAUX_PG: J1.57 U4.12 | length 2864
  Top Layer w10: U4.12@1441.72,1696.72 1441.72,1651.28 v2(1451,1642)
  S2 w10: v2(1451,1642) 1476,1642 1499,1619 1499,1430 1384,1315 1384,1132 1441,1075 2556,1075 2725,906 3106,906 3128,884 3128,693 3195.95,625.05 v2(3234.05,625.05)
  Bottom Layer w10: v2(3234.05,625.05) J1.57@3275.38,625.05
DAC_AVTT: C25A.2 C25B.2 C25C.2 C25D.2 C25E.2 C25F.2 C25G.2 C25H.2 C25I.2 C25J.2 C25K.2 J36.9 J130.9 R15.1 U5.3 U5.8 U5.9 U5.10 | length 530.4
  Top Layer w8: 1340,1314 1340,1414 1369,1443 1429.28,1443 1441.72,1430.57 U5.3@1441.72,1391.28 U5.3@1441.72,1390.28
  S2 w10: v2(1289,1318) 1289,1436 1333,1480 v2(1401,1480)
  Bottom Layer w10: v2(1401,1480) R15.1@1424,1480
  other v2: 916,1174 916,1224 966,1224 917,1274 966,1274 1016,1274 1066,1274 1116,1274 1166,1274 1216,1274 1266,1274
DAC_AVTT_FB: JP5.2 R15.2 U5.2 | length 152.3
  Top Layer w8: U5.2@1459.43,1390.28 U5.2@1459.43,1391.28 v2(1459.43,1443.57)
  Bottom Layer w8: v2(1459.43,1443.57) JP5.2@1459.43,1542.57
DAC_AVTT_PG: J1.55 U5.12 | length 2325.3
  Top Layer w10: U5.12@1441.72,1299.72 1441.72,1254.28 v2(1451,1245)
  S2 w10: v2(1451,1245) 1451,1179 1502,1128 2653,1128 2719,1062 3084,1062 3151.88,994.12 3151.88,715.12 3206.95,660.05 v2(3232.05,660.05)
  Bottom Layer w10: v2(3232.05,660.05) J1.55@3273.38,660.05
DAC_VCC: C103.2 R33.1 U3.6 U3.26 | length 648
  Top Layer w10: v2@1957,1495 U3.6@1987.38,1495 ; U3.26@2284.62,1443.82 v2(2320.82,1443.82)
  S2 w20: v2(1957,1496) 2002,1496 2021,1515 2021,1561 2058,1598 v2(2241,1598) 2289,1550 2289,1488 2320.82,1456.18 v2(2320.82,1443.82)
  Bottom Layer w20: v2@2241,1597 R33.1@2241,1638
EN: J1.69 R_EN.1 U1.31 U2.4 U3.31 U4.4 U5.4 | length 5324.9
  Top Layer w8: v2@1421,734 1424,731 U2.4@1424,700.28 U2.4@1424,699.28 ; v2@1421,1425 1424,1422 U5.4@1424,1391.28 U5.4@1424,1390.28 ; v2@1421,1822 1424,1819 U4.4@1424,1787.28 ; v2(1616,1834) R_EN.1@1636,1834 ; U3.31@2284.62,1571.77 v2(2330.77,1571.77) ; U1.31@2831.77,102.38 v2@2831.77,134.76
  S2 w8: v2(2330.77,1571.77) 2329.94,1571.77 2251.72,1650 1956,1650 1772,1834 v2(1616,1834) 1546,1834 1532,1820 v2(1421,1820) 1403,1802 1403,1527 1432,1498 1432,1434 v2(1421,1423) 1352,1354 1352,906 1429,829 1429,740 v2(1421,732) 1404,715 1404,494 1435,463 2178,463 2299,584 2660,584 2725,519 3219,519 3232.05,505.95 v2(3232.05,440.05) 3219,427 3029,427 3003,427 2984,408 2984,318 2949,283 2949,194 2875,120 2845,120 v2(2832,133)
  Bottom Layer w10: v2(3232.05,440.05) J1.69@3273.38,440.05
